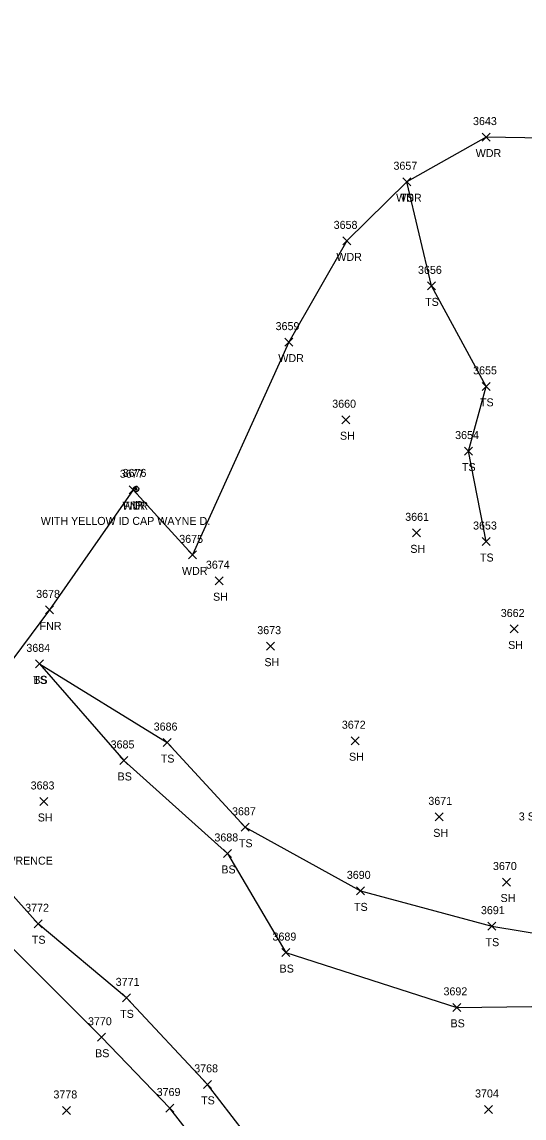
# Model space of a CAD drawing. Extents: x 1634209 to 1639641, y 608564 to 612258.
# Drawn here: x 1639067 to 1639192.5, y 611460.6 to 611734.6 of the extents above; entities that cross this region are included whole.
import ezdxf

# ---------------------------------------------------------------- set-up
doc = ezdxf.new("R2010")
doc.units = 0
for name, color, linetype in [('L_A', 7, 'Continuous'), ('L_C', 7, 'Continuous'), ('L_I', 7, 'Continuous'), ('L_TIC', 7, 'Continuous'), ('LAWA', 7, 'Continuous'), ('LELB', 7, 'Continuous'), ('LFNC', 7, 'Continuous'), ('M_A', 7, 'Continuous'), ('M_C', 7, 'Continuous'), ('M_I', 7, 'Continuous'), ('MPIR', 7, 'Continuous')]:
    doc.layers.add(name, color=color, linetype=linetype)

msp = doc.modelspace()

# ---------------------------------------------------------------- linework, layer by layer
at = {"layer": 'L_TIC'}
for points in [[(1639182.07, 611704.82), (1639184.07, 611706.82)], [(1639184.07, 611704.82), (1639182.07, 611706.82)], [(1639162.18, 611693.66), (1639164.18, 611695.66)], [(1639164.18, 611693.66), (1639162.18, 611695.66)], [(1639162.18, 611693.66), (1639164.18, 611695.66)], [(1639164.18, 611693.66), (1639162.18, 611695.66)], [(1639147.22, 611678.88), (1639149.22, 611680.88)], [(1639149.22, 611678.88), (1639147.22, 611680.88)], [(1639168.37, 611667.63), (1639170.37, 611669.63)], [(1639170.37, 611667.63), (1639168.37, 611669.63)], [(1639132.72, 611653.57), (1639134.72, 611655.57)], [(1639134.72, 611653.57), (1639132.72, 611655.57)], [(1639182.09, 611642.52), (1639184.09, 611644.52)], [(1639184.09, 611642.52), (1639182.09, 611644.52)], [(1639147, 611634.17), (1639149, 611636.17)], [(1639149, 611634.17), (1639147, 611636.17)], [(1639177.59, 611626.34), (1639179.59, 611628.34)], [(1639179.59, 611626.34), (1639177.59, 611628.34)], [(1639093.77, 611616.67), (1639095.77, 611618.67)], [(1639095.77, 611616.67), (1639093.77, 611618.67)], [(1639093.77, 611616.67), (1639095.77, 611618.67)], [(1639095.77, 611616.67), (1639093.77, 611618.67)], [(1639164.6, 611605.9), (1639166.6, 611607.9)], [(1639166.6, 611605.9), (1639164.6, 611607.9)], [(1639182.09, 611603.73), (1639184.09, 611605.73)], [(1639184.09, 611603.73), (1639182.09, 611605.73)], [(1639108.62, 611600.39), (1639110.62, 611602.39)], [(1639110.62, 611600.39), (1639108.62, 611602.39)], [(1639115.27, 611593.93), (1639117.27, 611595.93)], [(1639117.27, 611593.93), (1639115.27, 611595.93)], [(1639072.85, 611586.64), (1639074.85, 611588.64)], [(1639074.85, 611586.64), (1639072.85, 611588.64)], [(1639189.06, 611581.87), (1639191.06, 611583.87)], [(1639191.06, 611581.87), (1639189.06, 611583.87)], [(1639128.13, 611577.58), (1639130.13, 611579.58)], [(1639130.13, 611577.58), (1639128.13, 611579.58)], [(1639070.39, 611573.15), (1639072.39, 611575.15)], [(1639072.39, 611573.15), (1639070.39, 611575.15)], [(1639070.39, 611573.15), (1639072.39, 611575.15)], [(1639072.39, 611573.15), (1639070.39, 611575.15)], [(1639149.27, 611553.94), (1639151.27, 611555.94)], [(1639151.27, 611553.94), (1639149.27, 611555.94)], [(1639102.28, 611553.48), (1639104.28, 611555.48)], [(1639104.28, 611553.48), (1639102.28, 611555.48)], [(1639091.46, 611549.01), (1639093.46, 611551.01)], [(1639093.46, 611549.01), (1639091.46, 611551.01)], [(1639071.45, 611538.76), (1639073.45, 611540.76)], [(1639073.45, 611538.76), (1639071.45, 611540.76)], [(1639170.33, 611534.91), (1639172.33, 611536.91)], [(1639172.33, 611534.91), (1639170.33, 611536.91)], [(1639121.81, 611532.31), (1639123.81, 611534.31)], [(1639123.81, 611532.31), (1639121.81, 611534.31)], [(1639117.4, 611525.77), (1639119.4, 611527.77)], [(1639119.4, 611525.77), (1639117.4, 611527.77)], [(1639187.15, 611518.62), (1639189.15, 611520.62)], [(1639189.15, 611518.62), (1639187.15, 611520.62)], [(1639150.6, 611516.41), (1639152.6, 611518.41)], [(1639152.6, 611516.41), (1639150.6, 611518.41)], [(1639070.05, 611508.19), (1639072.05, 611510.19)], [(1639072.05, 611508.19), (1639070.05, 611510.19)], [(1639183.48, 611507.59), (1639185.48, 611509.59)], [(1639185.48, 611507.59), (1639183.48, 611509.59)], [(1639131.95, 611500.99), (1639133.95, 611502.99)], [(1639133.95, 611500.99), (1639131.95, 611502.99)], [(1639092.12, 611489.67), (1639094.12, 611491.67)], [(1639094.12, 611489.67), (1639092.12, 611491.67)], [(1639174.69, 611487.3), (1639176.69, 611489.3)], [(1639176.69, 611487.3), (1639174.69, 611489.3)], [(1639085.83, 611479.83), (1639087.83, 611481.83)], [(1639087.83, 611479.83), (1639085.83, 611481.83)], [(1639112.36, 611468.05), (1639114.36, 611470.05)], [(1639114.36, 611468.05), (1639112.36, 611470.05)], [(1639077.11, 611461.53), (1639079.11, 611463.53)], [(1639079.11, 611461.53), (1639077.11, 611463.53)], [(1639102.98, 611462.14), (1639104.98, 611464.14)], [(1639104.98, 611462.14), (1639102.98, 611464.14)], [(1639182.61, 611461.77), (1639184.61, 611463.77)], [(1639184.61, 611461.77), (1639182.61, 611463.77)]]:
    msp.add_lwpolyline(points, dxfattribs=at)
at = {"layer": 'LAWA'}
msp.add_lwpolyline([(1639360.4, 611945.78), (1639337.86, 611942.69), (1639328.3, 611925.99), (1639325.8, 611899.79), (1639322.13, 611876.77), (1639319.6, 611839.54), (1639313.3, 611808.51), (1639315.96, 611791.14), (1639292.51, 611779.22), (1639297.13, 611749.76), (1639287.19, 611716.77), (1639276.76, 611694.78), (1639243.82, 611692.54), (1639224.95, 611705.38), (1639202.4, 611705.49), (1639183.07, 611705.82), (1639163.18, 611694.66), (1639148.22, 611679.88), (1639133.72, 611654.57), (1639109.62, 611601.39), (1639094.77, 611617.67)], dxfattribs=at)
at = {"layer": 'LELB'}
for points in [[(1639183.09, 611604.73), (1639178.59, 611627.34), (1639183.09, 611643.52), (1639169.37, 611668.63), (1639163.18, 611694.66)], [(1639071.39, 611574.15), (1639103.28, 611554.48), (1639122.81, 611533.31), (1639151.6, 611517.41), (1639184.48, 611508.59), (1639215.32, 611503.5), (1639240.84, 611494.46), (1639241.1, 611484.62)], [(1639071.39, 611574.15), (1639092.46, 611550.01), (1639118.4, 611526.77), (1639132.95, 611501.99), (1639175.69, 611488.3), (1639200.72, 611488.61), (1639241.1, 611484.62)], [(1639184.5, 611390.62), (1639168.4, 611364.73), (1639149.1, 611336.39), (1639141.99, 611332.95), (1639134.34, 611331.83), (1639128.54, 611335.11), (1639121.61, 611339.72), (1639110.96, 611351.76), (1639096.78, 611371.21), (1639095.54, 611383.49), (1639101.79, 611394.14), (1639116.54, 611418.41), (1639131.91, 611444.98), (1639113.36, 611469.05), (1639093.12, 611490.67), (1639071.05, 611509.19), (1639055.5, 611526.42)], [(1639085.93, 611391.35), (1639090.7, 611396.06), (1639108.29, 611427.18), (1639120.56, 611441.89), (1639103.98, 611463.14), (1639086.83, 611480.83), (1639063.48, 611504.24), (1639051.54, 611519.63)]]:
    msp.add_lwpolyline(points, dxfattribs=at)
at = {"layer": 'LFNC'}
msp.add_lwpolyline([(1639094.77, 611617.67), (1639073.85, 611587.64), (1639057.58, 611565.93), (1639042.02, 611542.63), (1639054.27, 611527.1), (1639049.52, 611519.99), (1639048.6, 611519.1)], dxfattribs=at)
at = {"layer": 'MPIR'}
msp.add_lwpolyline([(1639095.51, 611618.22), (1639095.22, 611617.72), (1639095.8, 611617.72)], close=True, dxfattribs=at)
msp.add_circle((1639095.51, 611617.88), 0.667, dxfattribs=at)

# ---------------------------------------------------------------- texts
at = {"layer": 'L_A'}
for s, p in [('WDR', (1639180.43, 611700.82)), ('WDR', (1639160.54, 611689.66)), ('TS', (1639161.59, 611689.66)), ('WDR', (1639145.59, 611674.88)), ('TS', (1639167.78, 611663.63)), ('WDR', (1639131.08, 611649.57)), ('TS', (1639181.5, 611638.52)), ('SH', (1639146.49, 611630.17)), ('TS', (1639177, 611622.34)), ('WDR', (1639092.13, 611612.67)), ('FNR', (1639092.3, 611612.67)), ('SH', (1639164.08, 611601.9)), ('TS', (1639181.5, 611599.73)), ('WDR', (1639106.98, 611596.39)), ('SH', (1639114.76, 611589.93)), ('FNR', (1639071.39, 611582.64)), ('SH', (1639188.54, 611577.87)), ('SH', (1639127.61, 611573.58)), ('TS', (1639069.8, 611569.15)), ('BS', (1639069.83, 611569.15)), ('TS', (1639101.69, 611549.48)), ('SH', (1639148.75, 611549.94)), ('BS', (1639090.9, 611545.01)), ('SH', (1639070.94, 611534.76)), ('SH', (1639169.82, 611530.91)), ('TS', (1639121.22, 611528.31)), ('BS', (1639116.84, 611521.77)), ('SH', (1639186.64, 611514.62)), ('TS', (1639150.01, 611512.41)), ('TS', (1639069.46, 611504.19)), ('TS', (1639182.89, 611503.59)), ('BS', (1639131.39, 611496.99)), ('TS', (1639091.53, 611485.67)), ('BS', (1639174.13, 611483.3)), ('BS', (1639085.27, 611475.83)), ('TS', (1639111.77, 611464.05))]:
    msp.add_text(s, height=2, dxfattribs=at).set_placement(p)
at = {"layer": 'L_C'}
msp.add_text('3 SMALL ELMS', height=2, dxfattribs=at).set_placement((1639191.2, 611535.02))
at = {"layer": 'L_I'}
for s, p in [('3643', (1639179.76, 611708.82)), ('3657', (1639159.87, 611697.66)), ('3657', (1639159.87, 611697.66)), ('3658', (1639144.92, 611682.88)), ('3656', (1639166.01, 611671.63)), ('3659', (1639130.4, 611657.57)), ('3655', (1639179.79, 611646.52)), ('3660', (1639144.56, 611638.17)), ('3654', (1639175.29, 611630.34)), ('3677', (1639091.46, 611620.67)), ('3677', (1639091.46, 611620.67)), ('3661', (1639162.81, 611609.9)), ('3653', (1639179.78, 611607.73)), ('3675', (1639106.31, 611604.39)), ('3674', (1639112.97, 611597.93)), ('3678', (1639070.54, 611590.64)), ('3662', (1639186.7, 611585.87)), ('3673', (1639125.82, 611581.58)), ('3684', (1639068.08, 611577.15)), ('3684', (1639068.08, 611577.15)), ('3686', (1639099.92, 611557.48)), ('3672', (1639146.96, 611557.94)), ('3685', (1639089.15, 611553.01)), ('3683', (1639069.15, 611542.76)), ('3671', (1639168.59, 611538.91)), ('3687', (1639119.5, 611536.31)), ('3688', (1639115.1, 611529.77)), ('3670', (1639184.75, 611522.62)), ('3690', (1639148.21, 611520.41)), ('3772', (1639067.79, 611512.19)), ('3691', (1639181.74, 611511.59)), ('3689', (1639129.63, 611504.99)), ('3771', (1639090.42, 611493.67)), ('3692', (1639172.38, 611491.3)), ('3770', (1639083.49, 611483.83)), ('3768', (1639110.05, 611472.05)), ('3778', (1639074.85, 611465.53)), ('3769', (1639100.66, 611466.14)), ('3704', (1639180.27, 611465.77))]:
    msp.add_text(s, height=2, dxfattribs=at).set_placement(p)
at = {"layer": 'M_A'}
msp.add_text('IP', height=2, dxfattribs=at).set_placement((1639094.56, 611612.88))
at = {"layer": 'M_C'}
for s, p in [('WITH YELLOW ID CAP WAYNE D.', (1639071.69, 611608.88)), ('WITH CAP W LAWRENCE', (1639042.46, 611523.96))]:
    msp.add_text(s, height=2, dxfattribs=at).set_placement(p)
at = {"layer": 'M_I'}
msp.add_text('3676', height=2, dxfattribs=at).set_placement((1639092.15, 611620.88))

doc.saveas('drawing.dxf')
